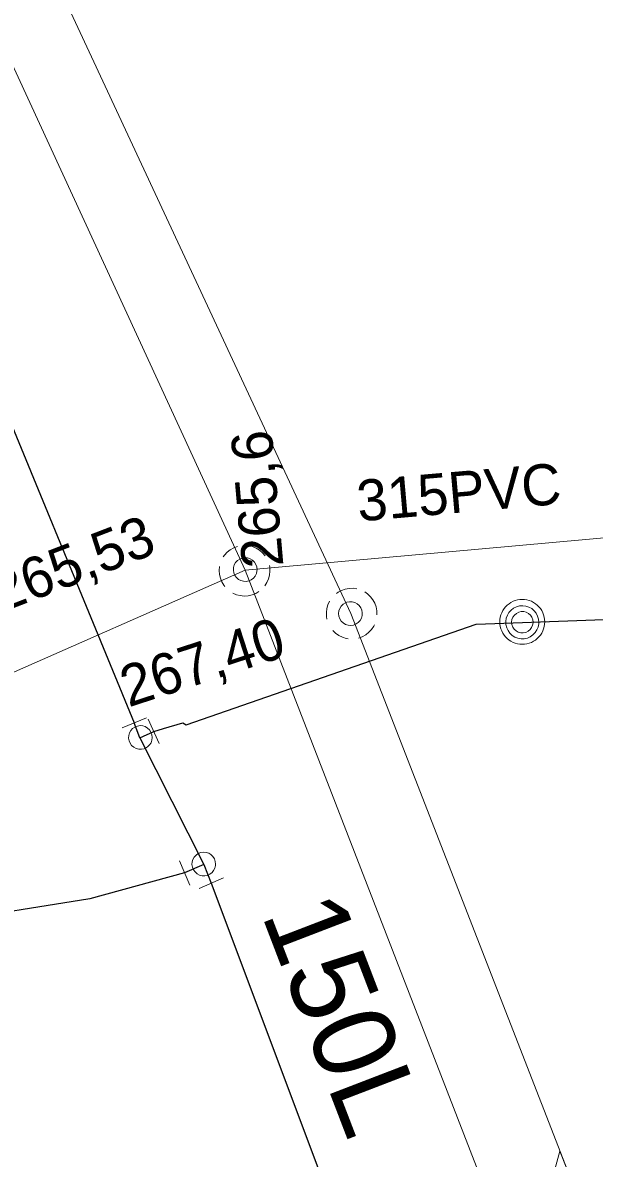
# Model space of a CAD drawing. Extents: x -732096 to -731933, y -1048703 to -1047964.
# Drawn here: x -732011.3 to -732000.17, y -1048554.73 to -1048532.64 of the extents above; entities that cross this region are included whole.
import ezdxf

# ---------------------------------------------------------------- set-up
doc = ezdxf.new("R2010")
doc.units = 0
doc.header["$LTSCALE"] = 0.32
doc.layers.add('1', color=7, linetype='Continuous')
for name, color, linetype, lineweight in [('18', 7, 'Continuous', 13), ('20', 7, 'Continuous', 13), ('8', 7, 'Continuous', 13)]:
    doc.layers.add(name, color=color, linetype=linetype, lineweight=lineweight)

msp = doc.modelspace()

# ---------------------------------------------------------------- linework, layer by layer
at = {"layer": '18'}
for points in [[(-732007.122, -1048542.827), (-732007.193, -1048542.855), (-732007.26, -1048542.894), (-732007.32, -1048542.942), (-732007.371, -1048542.999), (-732007.395, -1048543.033)], [(-732006.581, -1048543.01), (-732006.631, -1048542.952), (-732006.689, -1048542.902), (-732006.754, -1048542.861), (-732006.825, -1048542.832), (-732006.874, -1048542.818)], [(-732007.467, -1048543.219), (-732007.473, -1048543.296), (-732007.468, -1048543.373), (-732007.451, -1048543.448), (-732007.422, -1048543.519), (-732007.382, -1048543.585), (-732007.366, -1048543.607)], [(-732006.586, -1048543.596), (-732006.545, -1048543.531), (-732006.514, -1048543.461), (-732006.495, -1048543.386), (-732006.487, -1048543.31), (-732006.492, -1048543.233), (-732006.498, -1048543.198)], [(-732004.794, -1048543.653), (-732004.87, -1048543.643), (-732004.946, -1048543.645), (-732005.022, -1048543.659), (-732005.095, -1048543.684), (-732005.162, -1048543.721), (-732005.191, -1048543.741)], [(-732007.209, -1048543.736), (-732007.139, -1048543.767), (-732007.064, -1048543.786), (-732006.988, -1048543.793), (-732006.911, -1048543.788), (-732006.836, -1048543.771), (-732006.764, -1048543.743), (-732006.704, -1048543.708)], [(-732004.403, -1048544.158), (-732004.405, -1048544.082), (-732004.419, -1048544.006), (-732004.445, -1048543.934), (-732004.482, -1048543.866), (-732004.529, -1048543.806), (-732004.585, -1048543.752), (-732004.642, -1048543.713)], [(-732005.327, -1048543.896), (-732005.358, -1048543.966), (-732005.379, -1048544.039), (-732005.389, -1048544.116), (-732005.385, -1048544.192), (-732005.377, -1048544.243)], [(-732005.264, -1048544.464), (-732005.209, -1048544.516), (-732005.145, -1048544.56), (-732005.076, -1048544.594), (-732005.003, -1048544.617), (-732004.962, -1048544.624)], [(-732004.763, -1048544.611), (-732004.691, -1048544.584), (-732004.623, -1048544.547), (-732004.562, -1048544.499), (-732004.51, -1048544.443), (-732004.467, -1048544.379), (-732004.454, -1048544.355)], [(-732001.581, -1048555.709), (-732000.56, -1048555.312), (-732000.84, -1048554.594), (-732001.099, -1048555.522)]]:
    msp.add_lwpolyline(points, dxfattribs=at)
for points in [[(-732006.738, -1048543.279), (-732006.744, -1048543.227), (-732006.762, -1048543.177), (-732006.79, -1048543.133), (-732006.828, -1048543.096), (-732006.873, -1048543.069), (-732006.923, -1048543.053), (-732006.975, -1048543.048), (-732007.027, -1048543.055), (-732007.076, -1048543.074), (-732007.12, -1048543.104), (-732007.155, -1048543.143), (-732007.181, -1048543.188), (-732007.196, -1048543.239), (-732007.199, -1048543.291), (-732007.191, -1048543.343), (-732007.17, -1048543.391), (-732007.14, -1048543.434), (-732007.1, -1048543.469), (-732007.054, -1048543.493), (-732007.003, -1048543.507), (-732006.951, -1048543.509), (-732006.899, -1048543.499), (-732006.851, -1048543.477), (-732006.809, -1048543.445), (-732006.776, -1048543.405), (-732006.752, -1048543.358), (-732006.74, -1048543.307)], [(-732005.017, -1048543.925), (-732005.061, -1048543.952), (-732005.099, -1048543.989), (-732005.127, -1048544.033), (-732005.144, -1048544.083), (-732005.15, -1048544.136), (-732005.143, -1048544.188), (-732005.126, -1048544.237), (-732005.098, -1048544.281), (-732005.06, -1048544.318), (-732005.014, -1048544.345), (-732004.964, -1048544.36), (-732004.912, -1048544.365), (-732004.859, -1048544.357), (-732004.811, -1048544.337), (-732004.767, -1048544.308), (-732004.733, -1048544.269), (-732004.706, -1048544.223), (-732004.691, -1048544.172), (-732004.689, -1048544.121), (-732004.698, -1048544.068), (-732004.718, -1048544.02), (-732004.749, -1048543.978), (-732004.789, -1048543.943), (-732004.836, -1048543.919), (-732004.886, -1048543.906), (-732004.939, -1048543.904), (-732004.99, -1048543.915)]]:
    msp.add_lwpolyline(points, close=True, dxfattribs=at)
at = {"layer": '20'}
for p, q in [((-732004.91, -1048544.13), (-732020.46, -1048510.78)), ((-732004.91, -1048544.13), (-732020.46, -1048510.78)), ((-731997.949, -1048542.48), (-732006.969, -1048543.29)), ((-731997.949, -1048542.48), (-732006.969, -1048543.29)), ((-731996.42, -1048570.48), (-732006.969, -1048543.29)), ((-731996.42, -1048570.48), (-732006.969, -1048543.29)), ((-731994.199, -1048571.66), (-732004.91, -1048544.13)), ((-731994.199, -1048571.66), (-732004.91, -1048544.13))]:
    msp.add_line(p, q, dxfattribs=at)
for points in [[(-732006.969, -1048543.29), (-732012.87, -1048530.498), (-732018.316, -1048518.694), (-732022.17, -1048510.34)], [(-732006.969, -1048543.29), (-732012.87, -1048530.498), (-732018.316, -1048518.694), (-732022.17, -1048510.34)], [(-732019.71, -1048548.87), (-732017.166, -1048547.78), (-732006.969, -1048543.29)], [(-732019.71, -1048548.87), (-732017.166, -1048547.78), (-732006.969, -1048543.29)]]:
    msp.add_lwpolyline(points, dxfattribs=at)
at = {"layer": '8'}
for p, q in [((-732008.889, -1048546.161), (-732009.367, -1048546.358)), ((-732008.855, -1048546.192), (-732008.645, -1048546.665)), ((-732008.047, -1048549.418), (-732008.249, -1048548.942)), ((-732007.39, -1048549.277), (-732007.865, -1048549.482))]:
    msp.add_line(p, q, dxfattribs=at)
at = {"layer": '8', "lineweight": 25}
for p, q in [((-732009.02, -1048546.55), (-732009.129, -1048546.26)), ((-732009.02, -1048546.55), (-732008.75, -1048546.43)), ((-732009.02, -1048546.55), (-732007.776, -1048549.018)), ((-732007.776, -1048549.018), (-732008.149, -1048549.18)), ((-732007.776, -1048549.018), (-732007.629, -1048549.38))]:
    msp.add_line(p, q, dxfattribs=at)
for points in [[(-732043.199, -1048472.29), (-732042.854, -1048473.025), (-732034.093, -1048491.956), (-732023.079, -1048515.311), (-732013.932, -1048535.062), (-732012.27, -1048538.65), (-732009.129, -1048546.26)], [(-732001.568, -1048544.306), (-731995.059, -1048544.07), (-731994.09, -1048544.03)], [(-732008.75, -1048546.43), (-732008.559, -1048546.37), (-732008.18, -1048546.26), (-732008.12, -1048546.3), (-732002.469, -1048544.34), (-732001.568, -1048544.306)], [(-732008.149, -1048549.18), (-732009.997, -1048549.686), (-732015.672, -1048550.592), (-732028.62, -1048552.38)], [(-732007.629, -1048549.38), (-732002.27, -1048563.66), (-731996.51, -1048580.99), (-731995.102, -1048586.543), (-731992.07, -1048598.5), (-731991.625, -1048601.24), (-731990.239, -1048608.37)]]:
    msp.add_lwpolyline(points, dxfattribs=at)
at = {"layer": '8'}
msp.add_lwpolyline([(-732001.137, -1048544.295), (-732001.14, -1048544.25), (-732001.147, -1048544.205), (-732001.159, -1048544.16), (-732001.174, -1048544.118), (-732001.196, -1048544.077), (-732001.221, -1048544.038), (-732001.25, -1048544.003), (-732001.282, -1048543.97), (-732001.318, -1048543.942), (-732001.355, -1048543.917), (-732001.397, -1048543.896), (-732001.44, -1048543.879), (-732001.483, -1048543.867), (-732001.529, -1048543.86), (-732001.575, -1048543.858), (-732001.62, -1048543.86), (-732001.666, -1048543.867), (-732001.71, -1048543.879), (-732001.753, -1048543.896), (-732001.794, -1048543.917), (-732001.831, -1048543.942), (-732001.868, -1048543.97), (-732001.9, -1048544.003), (-732001.929, -1048544.038), (-732001.954, -1048544.077), (-732001.975, -1048544.118), (-732001.99, -1048544.16), (-732002.003, -1048544.205), (-732002.01, -1048544.25), (-732002.012, -1048544.296), (-732002.01, -1048544.341), (-732002.003, -1048544.386), (-732001.99, -1048544.431), (-732001.975, -1048544.473), (-732001.954, -1048544.514), (-732001.929, -1048544.553), (-732001.9, -1048544.588), (-732001.868, -1048544.621), (-732001.831, -1048544.649), (-732001.794, -1048544.674), (-732001.753, -1048544.695), (-732001.71, -1048544.712), (-732001.666, -1048544.723), (-732001.62, -1048544.731), (-732001.575, -1048544.733), (-732001.529, -1048544.731), (-732001.483, -1048544.723), (-732001.44, -1048544.712), (-732001.397, -1048544.695), (-732001.355, -1048544.674), (-732001.318, -1048544.649), (-732001.282, -1048544.621), (-732001.25, -1048544.588), (-732001.221, -1048544.553), (-732001.196, -1048544.514), (-732001.174, -1048544.473), (-732001.159, -1048544.431), (-732001.147, -1048544.386), (-732001.14, -1048544.341), (-732001.137, -1048544.296)], dxfattribs=at)
for points in [[(-732001.25, -1048544.303), (-732001.257, -1048544.242), (-732001.275, -1048544.182), (-732001.304, -1048544.127), (-732001.343, -1048544.079), (-732001.39, -1048544.039), (-732001.444, -1048544.009), (-732001.503, -1048543.989), (-732001.565, -1048543.982), (-732001.627, -1048543.986), (-732001.686, -1048544.002), (-732001.742, -1048544.03), (-732001.792, -1048544.067), (-732001.833, -1048544.114), (-732001.865, -1048544.167), (-732001.885, -1048544.226), (-732001.895, -1048544.287), (-732001.892, -1048544.349), (-732001.877, -1048544.409), (-732001.851, -1048544.466), (-732001.815, -1048544.516), (-732001.769, -1048544.559), (-732001.717, -1048544.591), (-732001.659, -1048544.614), (-732001.598, -1048544.624), (-732001.536, -1048544.623), (-732001.475, -1048544.61), (-732001.418, -1048544.585), (-732001.367, -1048544.55), (-732001.323, -1048544.506), (-732001.289, -1048544.454), (-732001.265, -1048544.397), (-732001.253, -1048544.336)], [(-732001.365, -1048544.303), (-732001.37, -1048544.254), (-732001.387, -1048544.207), (-732001.416, -1048544.166), (-732001.454, -1048544.133), (-732001.498, -1048544.109), (-732001.546, -1048544.097), (-732001.596, -1048544.096), (-732001.644, -1048544.108), (-732001.689, -1048544.13), (-732001.727, -1048544.163), (-732001.755, -1048544.203), (-732001.775, -1048544.25), (-732001.782, -1048544.299), (-732001.777, -1048544.349), (-732001.76, -1048544.396), (-732001.733, -1048544.438), (-732001.696, -1048544.472), (-732001.652, -1048544.496), (-732001.605, -1048544.51), (-732001.554, -1048544.511), (-732001.505, -1048544.501), (-732001.461, -1048544.479), (-732001.422, -1048544.447), (-732001.392, -1048544.408), (-732001.373, -1048544.362), (-732001.365, -1048544.312)], [(-732008.913, -1048546.755), (-732008.868, -1048546.727), (-732008.83, -1048546.69), (-732008.802, -1048546.646), (-732008.785, -1048546.596), (-732008.779, -1048546.544), (-732008.786, -1048546.492), (-732008.803, -1048546.442), (-732008.831, -1048546.398), (-732008.869, -1048546.362), (-732008.915, -1048546.334), (-732008.965, -1048546.319), (-732009.017, -1048546.314), (-732009.069, -1048546.322), (-732009.118, -1048546.342), (-732009.162, -1048546.371), (-732009.196, -1048546.41), (-732009.223, -1048546.455), (-732009.237, -1048546.506), (-732009.24, -1048546.558), (-732009.231, -1048546.61), (-732009.211, -1048546.658), (-732009.18, -1048546.701), (-732009.14, -1048546.736), (-732009.093, -1048546.76), (-732009.043, -1048546.773), (-732008.99, -1048546.775), (-732008.939, -1048546.765)], [(-732007.544, -1048549.007), (-732007.551, -1048548.955), (-732007.568, -1048548.905), (-732007.597, -1048548.861), (-732007.635, -1048548.824), (-732007.679, -1048548.797), (-732007.73, -1048548.781), (-732007.782, -1048548.776), (-732007.833, -1048548.783), (-732007.882, -1048548.802), (-732007.926, -1048548.832), (-732007.962, -1048548.871), (-732007.988, -1048548.916), (-732008.002, -1048548.967), (-732008.005, -1048549.019), (-732007.997, -1048549.071), (-732007.977, -1048549.119), (-732007.946, -1048549.162), (-732007.907, -1048549.197), (-732007.86, -1048549.221), (-732007.809, -1048549.235), (-732007.757, -1048549.237), (-732007.706, -1048549.227), (-732007.657, -1048549.205), (-732007.615, -1048549.173), (-732007.583, -1048549.133), (-732007.559, -1048549.086), (-732007.546, -1048549.035)]]:
    msp.add_lwpolyline(points, close=True, dxfattribs=at)

# ---------------------------------------------------------------- texts
at = {"layer": '1'}
for s, height, rotation, p in [('265,6 ', 0.8, 95, (-732006.223, -1048543.208)), ('315PVC', 0.8, 5, (-732004.76, -1048542.344)), ('265,53', 0.8, 21, (-732011.714, -1048544.118)), ('267,40', 0.8, 18, (-732009.24, -1048545.961)), ('150L', 1.6, 291, (-732006.658, -1048549.983))]:
    msp.add_text(s, height=height, rotation=rotation, dxfattribs=at).set_placement(p)

doc.saveas('drawing.dxf')
